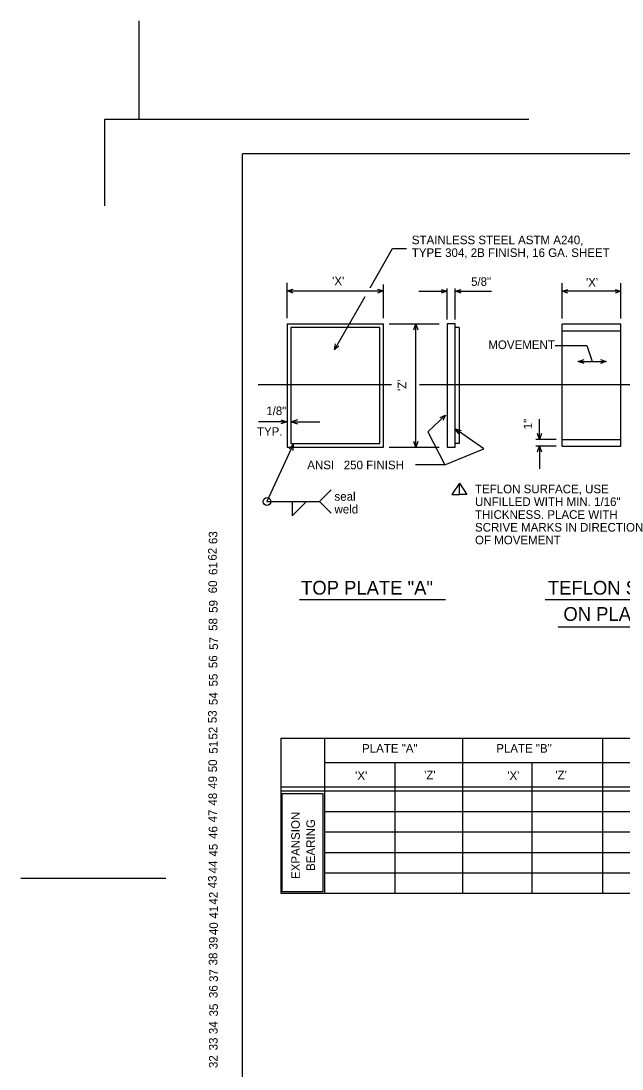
# Model space of a CAD drawing. Extents: x -1.11 to 1.91, y -1.43 to 1.11.
# Drawn here: x -1.114 to -0.387, y -0.154 to 1.113 of the extents above; entities that cross this region are included whole.
import ezdxf

# ---------------------------------------------------------------- set-up
doc = ezdxf.new("R2010")
doc.units = 0
for name, color, linetype in [('Level 1', 7, 'Continuous'), ('Level 2', 7, 'Continuous'), ('Level 32', 7, 'Continuous'), ('Level 33', 7, 'Continuous'), ('Level 34', 7, 'Continuous'), ('Level 35', 7, 'Continuous'), ('Level 36', 7, 'Continuous'), ('Level 37', 7, 'Continuous'), ('Level 38', 7, 'Continuous'), ('Level 39', 7, 'Continuous'), ('Level 40', 7, 'Continuous'), ('Level 41', 7, 'Continuous'), ('Level 42', 7, 'Continuous'), ('Level 43', 7, 'Continuous'), ('Level 44', 7, 'Continuous'), ('Level 45', 7, 'Continuous'), ('Level 46', 7, 'Continuous'), ('Level 47', 7, 'Continuous'), ('Level 48', 7, 'Continuous'), ('Level 49', 7, 'Continuous'), ('Level 50', 7, 'Continuous'), ('Level 51', 7, 'Continuous'), ('Level 52', 7, 'Continuous'), ('Level 53', 7, 'Continuous'), ('Level 54', 7, 'Continuous'), ('Level 55', 7, 'Continuous'), ('Level 56', 7, 'Continuous'), ('Level 57', 7, 'Continuous'), ('Level 58', 7, 'Continuous'), ('Level 59', 7, 'Continuous'), ('Level 60', 7, 'Continuous'), ('Level 61', 7, 'Continuous'), ('Level 62', 7, 'Continuous'), ('Level 63', 7, 'Continuous')]:
    doc.layers.add(name, color=color, linetype=linetype)

msp = doc.modelspace()

# ---------------------------------------------------------------- linework, layer by layer
at = {"layer": 'Level 1'}
for p, q in [((-0.4998, 0.9937), (-1.0128, 0.9937)), ((-1.0128, 0.9937), (-1.0128, 0.8892)), ((-0.846, -0.7994), (-0.846, 0.952)), ((1.7708, 0.952), (-0.846, 0.952))]:
    msp.add_line(p, q, dxfattribs=at)
at = {"layer": 'Level 2'}
for p, q in [((-0.9711, 0.9937), (-0.9711, 1.1127)), ((-0.6919, 0.7901), (-0.6646, 0.8377)), ((-0.6646, 0.8377), (-0.6477, 0.8377)), ((-0.7919, 0.7536), (-0.7919, 0.7961)), ((-0.7919, 0.7863), (-0.6758, 0.7863)), ((-0.6758, 0.7536), (-0.6758, 0.7943)), ((-0.6328, 0.7859), (-0.5988, 0.7859)), ((-0.5988, 0.7518), (-0.5988, 0.7894)), ((-0.589, 0.7518), (-0.589, 0.7894)), ((-0.589, 0.7859), (-0.5452, 0.7859)), ((-0.4597, 0.7532), (-0.4597, 0.7957)), ((-0.3885, 0.7859), (-0.4597, 0.7859)), ((-0.3885, 0.7532), (-0.3885, 0.7957)), ((-0.735, 0.715), (-0.6978, 0.7798)), ((-0.7919, 0.7465), (-0.7919, 0.5974)), ((-0.7919, 0.7465), (-0.6758, 0.7465)), ((-0.6802, 0.7421), (-0.7875, 0.7421)), ((-0.7875, 0.7421), (-0.7875, 0.6018)), ((-0.6802, 0.6018), (-0.6802, 0.7421)), ((-0.6758, 0.5974), (-0.6758, 0.7465)), ((-0.6688, 0.7465), (-0.6084, 0.7465)), ((-0.6367, 0.5974), (-0.6367, 0.7465)), ((-0.589, 0.7465), (-0.5988, 0.7465)), ((-0.5988, 0.7465), (-0.5988, 0.5974)), ((-0.589, 0.5974), (-0.589, 0.7465)), ((-0.5843, 0.7421), (-0.589, 0.7421)), ((-0.5843, 0.7421), (-0.5843, 0.6018)), ((-0.3885, 0.7461), (-0.4597, 0.7461)), ((-0.4597, 0.5989), (-0.4597, 0.7461)), ((-0.4597, 0.7382), (-0.3885, 0.7382)), ((-0.3885, 0.5989), (-0.3885, 0.7461)), ((-0.4681, 0.7204), (-0.4297, 0.7204)), ((-0.4297, 0.7204), (-0.4233, 0.701)), ((-0.4402, 0.701), (-0.4063, 0.701)), ((-0.8272, 0.6733), (-0.666, 0.6733)), ((-0.632, 0.6733), (-0.3766, 0.6733)), ((-0.6005, 0.6363), (-0.6221, 0.6159)), ((-0.7925, 0.6283), (-0.8266, 0.6283)), ((-0.7996, 0.6307), (-0.7925, 0.6283)), ((-0.7925, 0.6283), (-0.7996, 0.6258)), ((-0.7796, 0.6307), (-0.7867, 0.6283)), ((-0.7867, 0.6283), (-0.7526, 0.6283)), ((-0.7867, 0.6283), (-0.7796, 0.6258)), ((-0.487, 0.6068), (-0.487, 0.6315)), ((-0.6221, 0.6159), (-0.6013, 0.5763)), ((-0.5544, 0.5957), (-0.5888, 0.6197)), ((-0.7847, 0.6008), (-0.8165, 0.5318)), ((-0.7919, 0.5974), (-0.6758, 0.5974)), ((-0.7875, 0.6018), (-0.6802, 0.6018)), ((-0.6688, 0.5974), (-0.6084, 0.5974)), ((-0.6013, 0.5763), (-0.5544, 0.5957)), ((-0.5988, 0.5974), (-0.589, 0.5974)), ((-0.5843, 0.6018), (-0.589, 0.6018)), ((-0.4667, 0.6068), (-0.4915, 0.6068)), ((-0.4667, 0.5989), (-0.4915, 0.5989)), ((-0.487, 0.5989), (-0.487, 0.5715)), ((-0.4597, 0.6068), (-0.3885, 0.6068)), ((-0.4597, 0.5989), (-0.3885, 0.5989)), ((-0.6013, 0.5763), (-0.6369, 0.5763)), ((-0.7528, 0.5318), (-0.7387, 0.5459)), ((-0.8165, 0.5318), (-0.7528, 0.5318)), ((-0.7859, 0.5316), (-0.7859, 0.5144)), ((-0.7859, 0.5144), (-0.769, 0.5313)), ((-0.7528, 0.5318), (-0.7388, 0.5178)), ((-0.777, 0.4134), (-0.6005, 0.4134)), ((-0.4802, 0.4134), (-0.2806, 0.4134)), ((-0.4644, 0.3805), (-0.2958, 0.3805)), ((-0.7998, 0.246), (0.496, 0.246)), ((-0.7998, 0.246), (-0.7998, 0.0583)), ((-0.7468, 0.246), (-0.7468, 0.0583)), ((-0.5803, 0.246), (-0.5803, 0.0583)), ((-0.4108, 0.246), (-0.4108, 0.0583)), ((-0.7468, 0.2164), (0.0903, 0.2164)), ((-0.6621, 0.2164), (-0.6621, 0.0583)), ((-0.4961, 0.2164), (-0.4961, 0.0583)), ((-0.7998, 0.1869), (0.496, 0.1869)), ((-0.7998, 0.182), (-0.7468, 0.182)), ((-0.7521, 0.1869), (-0.7468, 0.1869)), ((-0.7468, 0.182), (0.496, 0.182)), ((-0.7468, 0.1573), (0.4953, 0.1573)), ((-0.7468, 0.1325), (0.496, 0.1325)), ((-0.7468, 0.1078), (0.4953, 0.1078)), ((-0.7468, 0.083), (0.496, 0.083)), ((-0.7998, 0.0583), (0.4953, 0.0583))]:
    msp.add_line(p, q, dxfattribs=at)
for points in [[(-0.7848, 0.7838), (-0.7919, 0.7863), (-0.7848, 0.7887)], [(-0.6828, 0.7887), (-0.6758, 0.7863), (-0.6828, 0.7838)], [(-0.6058, 0.7883), (-0.5988, 0.7859), (-0.6058, 0.7835)], [(-0.5819, 0.7835), (-0.589, 0.7859), (-0.5819, 0.7883)], [(-0.4526, 0.7835), (-0.4597, 0.7859), (-0.4526, 0.7883)], [(-0.3956, 0.7883), (-0.3885, 0.7859), (-0.3956, 0.7835)], [(-0.6391, 0.7394), (-0.6367, 0.7465), (-0.6343, 0.7394)], [(-0.7295, 0.7201), (-0.735, 0.715), (-0.7338, 0.7224)], [(-0.4331, 0.6986), (-0.4402, 0.701), (-0.4331, 0.7035)], [(-0.4134, 0.7035), (-0.4063, 0.701), (-0.4134, 0.6986)], [(-0.6073, 0.6332), (-0.6005, 0.6363), (-0.6039, 0.6297)], [(-0.5844, 0.6137), (-0.5888, 0.6197), (-0.5817, 0.6177)], [(-0.4846, 0.6139), (-0.487, 0.6068), (-0.4895, 0.6139)], [(-0.7898, 0.5954), (-0.7847, 0.6008), (-0.7854, 0.5934)], [(-0.6343, 0.6045), (-0.6367, 0.5974), (-0.6391, 0.6045)], [(-0.4895, 0.5918), (-0.487, 0.5989), (-0.4846, 0.5918)], [(-0.5839, 0.5542), (-0.5931, 0.5402), (-0.5839, 0.5402)], [(-0.5839, 0.5542), (-0.5748, 0.5402), (-0.5839, 0.5402)]]:
    msp.add_lwpolyline(points, dxfattribs=at)
for points in [[(-0.5839, 0.5542), (-0.5748, 0.5402), (-0.5839, 0.5402)], [(-0.7983, 0.1789), (-0.749, 0.1789), (-0.749, 0.0601), (-0.7983, 0.0601)]]:
    msp.add_lwpolyline(points, close=True, dxfattribs=at)
msp.add_circle((-0.8165, 0.5318), 0.00472, dxfattribs=at)
at = {"layer": 'Level 37'}
msp.add_line((-0.9389, 0.0763), (-1.114, 0.0763), dxfattribs=at)

# ---------------------------------------------------------------- texts
at = {"layer": 'Level 2'}
for s, height, p in [('STAINLESS STEEL ASTM A240,', 0.010417, (-0.6414, 0.8428)), ('TYPE 304, 2B FINISH, 16 GA. SHEET', 0.010417, (-0.6414, 0.8274)), ("'X'", 0.01042, (-0.7377, 0.7933)), ('5/8"', 0.01033, (-0.5697, 0.7925)), ("'X'", 0.01042, (-0.4308, 0.7916)), ('MOVEMENT', 0.01042, (-0.5489, 0.7161)), ('1/8"', 0.01033, (-0.8173, 0.6363)), ('TYP.', 0.01033, (-0.8285, 0.6113)), ('ANSI   250 FINISH', 0.010417, (-0.7678, 0.5708)), ('TEFLON SURFACE, USE', 0.010417, (-0.565, 0.5418)), ('seal', 0.01042, (-0.7349, 0.5328)), ('UNFILLED WITH MIN. 1/16"', 0.010417, (-0.565, 0.5264)), ('weld', 0.01042, (-0.7349, 0.5174)), ('THICKNESS. PLACE WITH', 0.010417, (-0.565, 0.5109)), ('SCRIVE MARKS IN DIRECTION', 0.010417, (-0.565, 0.4955)), ('OF MOVEMENT', 0.010417, (-0.565, 0.4801)), ('TOP PLATE "A"', 0.016667, (-0.7753, 0.4193)), ('TEFLON SURFACE', 0.016667, (-0.4769, 0.4193)), ('ON PLATE "B"', 0.016667, (-0.4581, 0.3876)), ('PLATE "A"', 0.0104, (-0.7015, 0.2283)), ('PLATE "B"', 0.0104, (-0.5393, 0.2283)), ("'X'", 0.0104, (-0.7099, 0.1954)), ("'Z'", 0.0104, (-0.6264, 0.1962)), ("'X'", 0.0104, (-0.5259, 0.1954)), ("'Z'", 0.0104, (-0.4678, 0.1962))]:
    msp.add_text(s, height=height, dxfattribs=at).set_placement(p)
for s, height, p in [("'Z'", 0.01042, (-0.6481, 0.6654)), ('1"', 0.01042, (-0.4959, 0.6191)), ('EXPANSION', 0.0104, (-0.7768, 0.0757)), ('BEARING', 0.0104, (-0.7585, 0.0854))]:
    msp.add_text(s, height=height, rotation=90, dxfattribs=at).set_placement(p)
at = {"layer": 'Level 32'}
msp.add_text('32', height=0.01041, rotation=90, dxfattribs=at).set_placement((-0.8762, -0.1529))
at = {"layer": 'Level 33'}
msp.add_text('33', height=0.01041, rotation=90, dxfattribs=at).set_placement((-0.8762, -0.1315))
at = {"layer": 'Level 34'}
msp.add_text('34', height=0.01041, rotation=90, dxfattribs=at).set_placement((-0.8762, -0.1119))
at = {"layer": 'Level 35'}
msp.add_text('35', height=0.01041, rotation=90, dxfattribs=at).set_placement((-0.8758, -0.0905))
at = {"layer": 'Level 36'}
msp.add_text('36', height=0.01041, rotation=90, dxfattribs=at).set_placement((-0.8762, -0.0683))
at = {"layer": 'Level 37'}
msp.add_text('37', height=0.01041, rotation=90, dxfattribs=at).set_placement((-0.8758, -0.0488))
at = {"layer": 'Level 38'}
msp.add_text('38', height=0.01041, rotation=90, dxfattribs=at).set_placement((-0.8765, -0.0288))
at = {"layer": 'Level 39'}
msp.add_text('39', height=0.01041, rotation=90, dxfattribs=at).set_placement((-0.8762, -0.0096))
at = {"layer": 'Level 40'}
msp.add_text('40', height=0.01041, rotation=90, dxfattribs=at).set_placement((-0.8758, 0.0078))
at = {"layer": 'Level 41'}
msp.add_text('41', height=0.01041, rotation=90, dxfattribs=at).set_placement((-0.8758, 0.0277))
at = {"layer": 'Level 42'}
msp.add_text('42', height=0.01041, rotation=90, dxfattribs=at).set_placement((-0.8762, 0.0447))
at = {"layer": 'Level 43'}
msp.add_text('43', height=0.01041, rotation=90, dxfattribs=at).set_placement((-0.8773, 0.0643))
at = {"layer": 'Level 44'}
msp.add_text('44', height=0.01041, rotation=90, dxfattribs=at).set_placement((-0.8765, 0.0823))
at = {"layer": 'Level 45'}
msp.add_text('45', height=0.01041, rotation=90, dxfattribs=at).set_placement((-0.8762, 0.1027))
at = {"layer": 'Level 46'}
msp.add_text('46', height=0.01041, rotation=90, dxfattribs=at).set_placement((-0.8765, 0.1241))
at = {"layer": 'Level 47'}
msp.add_text('47', height=0.01041, rotation=90, dxfattribs=at).set_placement((-0.8769, 0.144))
at = {"layer": 'Level 48'}
msp.add_text('48', height=0.01041, rotation=90, dxfattribs=at).set_placement((-0.8769, 0.1643))
at = {"layer": 'Level 49'}
msp.add_text('49', height=0.01041, rotation=90, dxfattribs=at).set_placement((-0.8769, 0.1846))
at = {"layer": 'Level 50'}
msp.add_text('50', height=0.01041, rotation=90, dxfattribs=at).set_placement((-0.8769, 0.2046))
at = {"layer": 'Level 51'}
msp.add_text('51', height=0.01041, rotation=90, dxfattribs=at).set_placement((-0.8762, 0.2271))
at = {"layer": 'Level 52'}
msp.add_text('52', height=0.01041, rotation=90, dxfattribs=at).set_placement((-0.8765, 0.2441))
at = {"layer": 'Level 53'}
msp.add_text('53', height=0.01041, rotation=90, dxfattribs=at).set_placement((-0.8773, 0.264))
at = {"layer": 'Level 54'}
msp.add_text('54', height=0.01041, rotation=90, dxfattribs=at).set_placement((-0.8762, 0.2858))
at = {"layer": 'Level 55'}
msp.add_text('55', height=0.01041, rotation=90, dxfattribs=at).set_placement((-0.8762, 0.3083))
at = {"layer": 'Level 56'}
msp.add_text('56', height=0.01041, rotation=90, dxfattribs=at).set_placement((-0.8765, 0.3305))
at = {"layer": 'Level 57'}
msp.add_text('57', height=0.01041, rotation=90, dxfattribs=at).set_placement((-0.8758, 0.3526))
at = {"layer": 'Level 58'}
msp.add_text('58', height=0.01041, rotation=90, dxfattribs=at).set_placement((-0.8765, 0.3755))
at = {"layer": 'Level 59'}
msp.add_text('59', height=0.01041, rotation=90, dxfattribs=at).set_placement((-0.8762, 0.3973))
at = {"layer": 'Level 60'}
msp.add_text('60', height=0.01041, rotation=90, dxfattribs=at).set_placement((-0.8769, 0.4209))
at = {"layer": 'Level 61'}
msp.add_text('61', height=0.01041, rotation=90, dxfattribs=at).set_placement((-0.8765, 0.4431))
at = {"layer": 'Level 62'}
msp.add_text('62', height=0.01041, rotation=90, dxfattribs=at).set_placement((-0.8773, 0.4604))
at = {"layer": 'Level 63'}
msp.add_text('63', height=0.01041, rotation=90, dxfattribs=at).set_placement((-0.8765, 0.4804))

doc.saveas('drawing.dxf')
